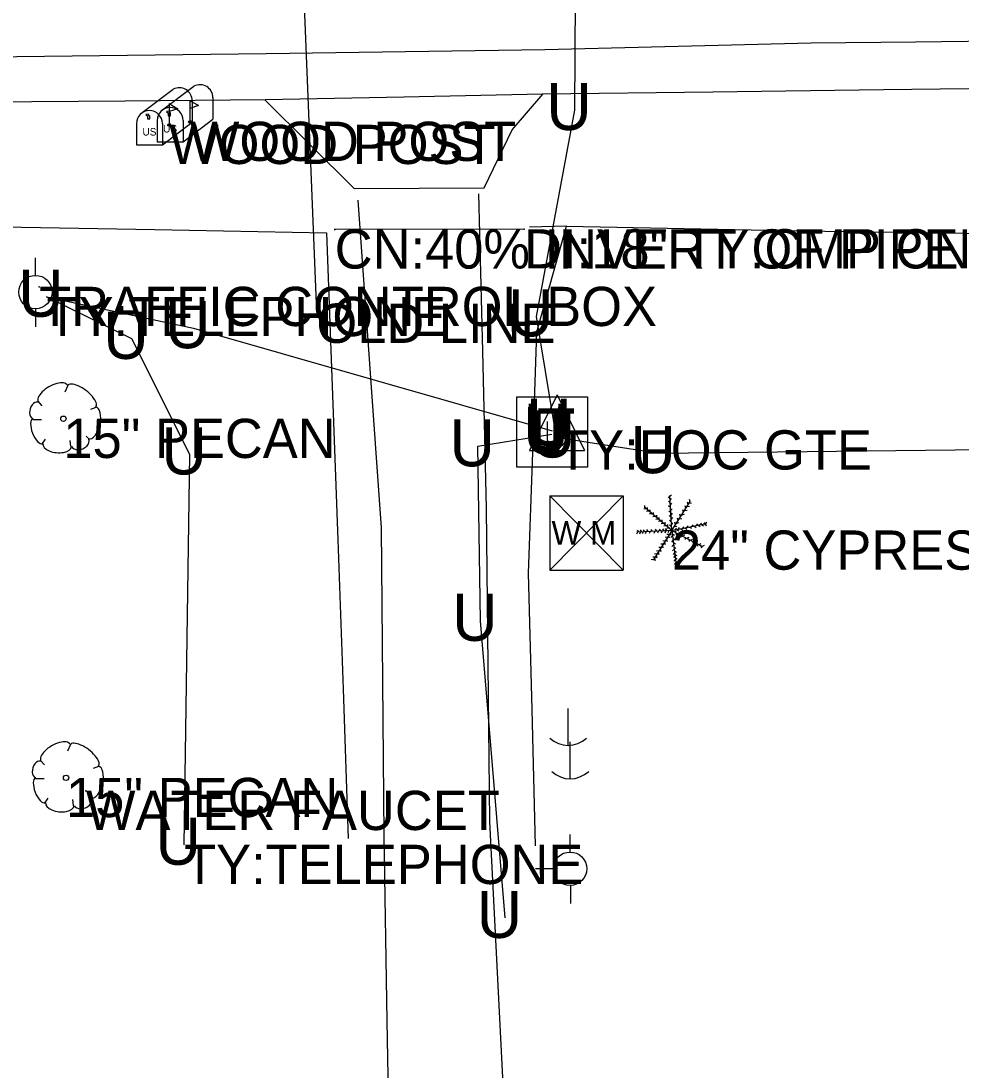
# Model space of a CAD drawing. Extents: x 1800653 to 1804042, y 522635 to 523313.
# Drawn here: x 1802896.5 to 1803016.3, y 522853.9 to 522987.6 of the extents above; entities that cross this region are included whole.
import ezdxf

# ---------------------------------------------------------------- set-up
doc = ezdxf.new("R2010")
doc.units = 0
for name, color, linetype in [('Default', 7, 'Continuous'), ('S_DITCHLINE', 7, 'Continuous'), ('S_DRG_PT_SYM', 7, 'Continuous'), ('S_EDGE_PAVEMENT', 7, 'Continuous'), ('S_GRAVEL_ROAD', 7, 'Continuous'), ('S_MAILBOX', 7, 'Continuous'), ('S_MAILBOX_ANNOT', 7, 'Continuous'), ('S_MSC_PT_SYM', 7, 'Continuous'), ('S_SANITARY_SEWER', 7, 'Continuous'), ('S_SANITARY_SEWER_ANNOT', 7, 'Continuous'), ('S_SHOULDER', 7, 'Continuous'), ('S_SIDE_DRAIN', 7, 'Continuous'), ('S_SIDE_DRAIN_ANNOT', 7, 'Continuous'), ('S_SURVEY_TEXT_ANNOT', 7, 'Continuous'), ('S_TELEPHONE_UTILITIES', 7, 'Continuous'), ('S_TREE', 7, 'Continuous'), ('S_TREE_ANNOT', 7, 'Continuous'), ('S_UNDERGROUND_CABLE', 7, 'Continuous'), ('S_UNDERGROUND_CABLE_ANNOT', 7, 'Continuous'), ('S_UTILITY_POLE', 7, 'Continuous'), ('S_UTILITY_POLE_ANNOT', 7, 'Continuous'), ('S_UTL_PT_SYM', 7, 'Continuous'), ('S_WATER_UTILITIES', 7, 'Continuous')]:
    doc.layers.add(name, color=color, linetype=linetype)

msp = doc.modelspace()

# ---------------------------------------------------------------- linework, layer by layer
at = {"layer": 'S_DITCHLINE'}
for points in [[(1802794.52, 522958.95), (1802809.08, 522959.6), (1802832.38, 522959.97), (1802855.67, 522960.34), (1802873.68, 522960.89), (1802891.69, 522961.44), (1802913.57, 522961.04), (1802935.44, 522960.63), (1802936.18, 522941.07), (1802936.91, 522921.5), (1802937.57, 522902.46), (1802938.23, 522883.42)], [(1802962.08, 522882.48), (1802961.64, 522899.88), (1802961.2, 522917.27), (1802961.74, 522932.63), (1802962.27, 522947.99), (1802966.05, 522961.46), (1802981.02, 522961.17), (1802996, 522960.89), (1803019.65, 522960.53), (1803023.7, 522960.83)], [(1802966.08, 522961.47), (1802961.32, 522961.36)]]:
    msp.add_lwpolyline(points, dxfattribs=at)
at = {"layer": 'S_DRG_PT_SYM'}
for points in [[(1802936.49, 522961.07), (1802936.49, 522961.12), (1802936.49, 522961.07), (1802936.44, 522961.07), (1802936.49, 522961.07), (1802936.49, 522961.02), (1802936.49, 522961.07), (1802936.54, 522961.07)], [(1802960.64, 522961.09), (1802960.64, 522961.14), (1802960.64, 522961.09), (1802960.59, 522961.09), (1802960.64, 522961.09), (1802960.64, 522961.04), (1802960.64, 522961.09), (1802960.69, 522961.09)]]:
    msp.add_lwpolyline(points, dxfattribs=at)
at = {"layer": 'S_EDGE_PAVEMENT'}
for points in [[(1802793.98, 522981.33), (1802808.56, 522981.56), (1802832.98, 522981.95), (1802857.39, 522982.34), (1802874.9, 522982.71), (1802892.4, 522983.08), (1802910.08, 522983.28), (1802927.76, 522983.47), (1802945.52, 522983.73), (1802963.29, 522983.99), (1802980.26, 522984.41), (1802997.22, 522984.84), (1803010.53, 522984.99), (1803023.83, 522985.13), (1803037.14, 522985.28), (1803050.45, 522985.42), (1803063.93, 522985.65), (1803077.42, 522985.88), (1803090.9, 522986.1), (1803104.39, 522986.33), (1803117.62, 522986.56), (1803130.85, 522986.79), (1803144.08, 522987.01)], [(1802927.57, 522977.59), (1802938.97, 522966.27), (1802955.56, 522966.37), (1802959.12, 522973.75), (1802963.01, 522978.32)]]:
    msp.add_lwpolyline(points, dxfattribs=at)
at = {"layer": 'S_GRAVEL_ROAD'}
for points in [[(1802939.44, 522964.79), (1802940.92, 522943.92), (1802942.41, 522923.04), (1802942.58, 522903.43), (1802942.74, 522883.82), (1802943.15, 522860.2), (1802943.56, 522836.59), (1802944.03, 522816.43), (1802944.5, 522796.27), (1802944.97, 522776.11), (1802945.44, 522755.95), (1802945.78, 522741.87), (1802946.11, 522727.8), (1802946.44, 522713.72), (1802946.77, 522699.64)], [(1802954.81, 522965.58), (1802955.31, 522945.54), (1802955.81, 522925.5), (1802956.03, 522905.55), (1802956.24, 522885.61), (1802957.46, 522861.32), (1802958.68, 522837.04), (1802958.8, 522823.18), (1802958.92, 522809.31), (1802959.04, 522795.45), (1802959.17, 522781.58), (1802958.84, 522768.07), (1802958.52, 522754.56), (1802958.93, 522740.82), (1802959.34, 522727.07), (1802959.75, 522713.32), (1802960.16, 522699.58)]]:
    msp.add_lwpolyline(points, dxfattribs=at)
at = {"layer": 'S_MAILBOX'}
for p, q in [((1802914.41, 522976.21), (1802918.55, 522979.32)), ((1802911.78, 522975.83), (1802915.91, 522978.94)), ((1802915.39, 522977.12), (1802915.39, 522974.4)), ((1802918.03, 522977.5), (1802918.03, 522974.79)), ((1802918.34, 522977.46), (1802918.34, 522974.75)), ((1802920.98, 522977.85), (1802920.98, 522975.13)), ((1802911.22, 522974.55), (1802911.22, 522971.84)), ((1802913.86, 522974.94), (1802913.86, 522972.22)), ((1802914.55, 522971.84), (1802918.34, 522974.75)), ((1802914.55, 522974.55), (1802914.55, 522971.84)), ((1802917.18, 522972.22), (1802920.98, 522975.13)), ((1802917.18, 522974.94), (1802917.18, 522972.22)), ((1802911.22, 522971.84), (1802914.55, 522971.84)), ((1802913.86, 522972.22), (1802917.18, 522972.22))]:
    msp.add_line(p, q, dxfattribs=at)
for points in [[(1802915.39, 522977.12), (1802916.5, 522976.45), (1802915.39, 522976.11)], [(1802918.03, 522977.5), (1802919.14, 522976.84), (1802918.03, 522976.49)], [(1802912.41, 522975.67), (1802912.63, 522975.53), (1802912.63, 522975.14), (1802912.93, 522975.14), (1802912.93, 522975.5), (1802912.74, 522975.75), (1802912.41, 522975.7)], [(1802915.04, 522976.05), (1802915.27, 522975.92), (1802915.27, 522975.53), (1802915.57, 522975.53), (1802915.57, 522975.89), (1802915.38, 522976.14), (1802915.04, 522976.08)]]:
    msp.add_lwpolyline(points, dxfattribs=at)
for centre, end in [((1802919.32, 522977.85), 117.5718), ((1802916.68, 522977.46), 117.5718), ((1802915.52, 522974.94), 180), ((1802912.88, 522974.55), 180)]:
    msp.add_arc(centre, 1.66, 0, end, dxfattribs=at)
for centre in [(1802915.39, 522974.4), (1802918.03, 522974.79)]:
    msp.add_ellipse(centre, major_axis=(0.145, 0.132), ratio=0.564646, dxfattribs=at)
at = {"layer": 'S_MSC_PT_SYM'}
for points in [[(1802898.82, 522953.75), (1802898.82, 522953.8), (1802898.82, 522953.75), (1802898.77, 522953.75), (1802898.82, 522953.75), (1802898.82, 522953.7), (1802898.82, 522953.75), (1802898.87, 522953.75)], [(1802904.79, 522889.51), (1802904.79, 522889.56), (1802904.79, 522889.51), (1802904.74, 522889.51), (1802904.79, 522889.51), (1802904.79, 522889.46), (1802904.79, 522889.51), (1802904.84, 522889.51)]]:
    msp.add_lwpolyline(points, dxfattribs=at)
at = {"layer": 'S_SANITARY_SEWER'}
msp.add_line((1802934.16, 522951.6), (1802931.11, 523028.65), dxfattribs=at)
at = {"layer": 'S_SHOULDER'}
msp.add_lwpolyline([(1802793.86, 522975.94), (1802808.36, 522976.14), (1802832.74, 522976.63), (1802857.12, 522977.13), (1802874.52, 522977.23), (1802891.91, 522977.33), (1802909.78, 522977.47), (1802927.64, 522977.61), (1802945.31, 522977.97), (1802962.99, 522978.33), (1802984.7, 522978.6), (1803006.42, 522978.88), (1803028.14, 522979.15), (1803049.85, 522979.42), (1803063.55, 522979.76), (1803077.25, 522980.09), (1803090.95, 522980.43), (1803104.65, 522980.76), (1803117.85, 522980.81), (1803131.05, 522980.86), (1803144.24, 522980.9)], dxfattribs=at)
at = {"layer": 'S_SIDE_DRAIN'}
msp.add_line((1802960.64, 522961.09), (1802936.49, 522961.07), dxfattribs=at)
at = {"layer": 'S_TELEPHONE_UTILITIES'}
msp.add_lwpolyline([(1802959.72, 522930.74), (1802959.72, 522939.74), (1802968.72, 522939.74), (1802968.72, 522930.74)], close=True, dxfattribs=at)
at = {"layer": 'S_TREE'}
for p, q in [((1802902.47, 522941.17), (1802902.08, 522940.32)), ((1802898.67, 522939.16), (1802899.18, 522938.58)), ((1802906.04, 522938.38), (1802905.38, 522938.11)), ((1802898.01, 522936.83), (1802899.14, 522936.83)), ((1802899.18, 522933.65), (1802899.64, 522934.35)), ((1802902.86, 522933.38), (1802902.78, 522934.16)), ((1802905.26, 522934.27), (1802904.8, 522934.7)), ((1802979.47, 522922.69), (1802979.2, 522927.13)), ((1802979.21, 522927.02), (1802979.4, 522927.25)), ((1802976.04, 522925.57), (1802976.04, 522925.87)), ((1802979.21, 522926.77), (1802978.99, 522926.97)), ((1802979.25, 522926.21), (1802979.02, 522926.41)), ((1802979.28, 522925.63), (1802979.05, 522925.83)), ((1802979.24, 522926.54), (1802979.43, 522926.77)), ((1802979.27, 522925.94), (1802979.46, 522926.17)), ((1802979.47, 522922.69), (1802981.81, 522926.37)), ((1802981.24, 522925.55), (1802981.15, 522925.83)), ((1802981.43, 522925.74), (1802981.73, 522925.78)), ((1802981.54, 522926), (1802981.45, 522926.29)), ((1802981.68, 522926.16), (1802981.97, 522926.2)), ((1802981.79, 522926.34), (1802981.7, 522926.63)), ((1802976.19, 522925.43), (1802975.89, 522925.39)), ((1802979.47, 522922.69), (1802976.01, 522925.6)), ((1802976.53, 522925.15), (1802976.23, 522925.13)), ((1802976.36, 522925.32), (1802976.36, 522925.62)), ((1802976.9, 522924.83), (1802976.6, 522924.81)), ((1802976.71, 522925.03), (1802976.71, 522925.33)), ((1802977.35, 522924.46), (1802977.05, 522924.43)), ((1802977.13, 522924.67), (1802977.13, 522924.97)), ((1802977.54, 522924.34), (1802977.54, 522924.64)), ((1802979.3, 522924.97), (1802979.08, 522925.17)), ((1802979.34, 522924.38), (1802979.12, 522924.58)), ((1802979.31, 522925.23), (1802979.5, 522925.46)), ((1802979.38, 522924.66), (1802979.56, 522924.9)), ((1802980.57, 522924.46), (1802980.48, 522924.75)), ((1802980.79, 522924.7), (1802981.08, 522924.75)), ((1802980.95, 522925.03), (1802980.86, 522925.32)), ((1802981.11, 522925.24), (1802981.41, 522925.29)), ((1802977.71, 522924.13), (1802977.42, 522924.1)), ((1802978.05, 522923.86), (1802977.75, 522923.84)), ((1802977.86, 522924.06), (1802977.86, 522924.36)), ((1802978.39, 522923.57), (1802978.09, 522923.54)), ((1802978.23, 522923.75), (1802978.23, 522924.05)), ((1802978.76, 522923.27), (1802978.46, 522923.25)), ((1802978.6, 522923.45), (1802978.6, 522923.75)), ((1802978.95, 522923.14), (1802978.95, 522923.44)), ((1802979.38, 522923.81), (1802979.15, 522924.01)), ((1802979.39, 522923.19), (1802979.17, 522923.39)), ((1802979.39, 522924.09), (1802979.58, 522924.33)), ((1802979.41, 522923.42), (1802979.6, 522923.66)), ((1802979.47, 522922.69), (1802983.89, 522923.56)), ((1802979.82, 522923.18), (1802980.11, 522923.22)), ((1802979.91, 522923.44), (1802979.83, 522923.73)), ((1802980.1, 522923.64), (1802980.4, 522923.69)), ((1802980.28, 522923.97), (1802980.19, 522924.26)), ((1802980.44, 522924.19), (1802980.73, 522924.23)), ((1802980.78, 522922.94), (1802980.98, 522923.16)), ((1802981.34, 522923.07), (1802981.54, 522923.29)), ((1802981.73, 522923.13), (1802981.98, 522922.97)), ((1802981.98, 522923.21), (1802982.18, 522923.43)), ((1802982.31, 522923.23), (1802982.56, 522923.07)), ((1802982.57, 522923.3), (1802982.77, 522923.52)), ((1802982.82, 522923.35), (1802983.07, 522923.19)), ((1802983.05, 522923.4), (1802983.25, 522923.62)), ((1802983.24, 522923.44), (1802983.5, 522923.28)), ((1802983.5, 522923.49), (1802983.7, 522923.71)), ((1802983.65, 522923.5), (1802983.9, 522923.34)), ((1802983.72, 522923.54), (1802983.93, 522923.76)), ((1802975.1, 522922.48), (1802974.97, 522922.21)), ((1802979.47, 522922.69), (1802975.02, 522922.48)), ((1802975.25, 522922.5), (1802975.08, 522922.75)), ((1802975.45, 522922.5), (1802975.32, 522922.23)), ((1802975.64, 522922.53), (1802975.47, 522922.77)), ((1802975.79, 522922.52), (1802975.66, 522922.25)), ((1802976.04, 522922.53), (1802975.87, 522922.77)), ((1802976.21, 522922.54), (1802976.08, 522922.27)), ((1802976.44, 522922.55), (1802976.27, 522922.8)), ((1802976.72, 522922.56), (1802976.59, 522922.29)), ((1802977.01, 522922.57), (1802976.84, 522922.81)), ((1802979.47, 522922.69), (1802977.09, 522918.92)), ((1802977.28, 522922.59), (1802977.15, 522922.32)), ((1802977.56, 522922.6), (1802977.39, 522922.85)), ((1802977.77, 522922.61), (1802977.63, 522922.34)), ((1802978.04, 522922.62), (1802977.87, 522922.87)), ((1802978.24, 522922.63), (1802978.1, 522922.36)), ((1802978.48, 522922.66), (1802978.31, 522922.9)), ((1802978.7, 522922.64), (1802978.56, 522922.37)), ((1802978.9, 522921.83), (1802978.6, 522921.79)), ((1802978.81, 522922.69), (1802978.64, 522922.94)), ((1802979.12, 522922.97), (1802978.82, 522922.95)), ((1802979.14, 522922.19), (1802978.84, 522922.16)), ((1802979.08, 522922.65), (1802978.95, 522922.38)), ((1802979.05, 522922.03), (1802979.13, 522921.74)), ((1802979.26, 522922.37), (1802979.34, 522922.08)), ((1802979.53, 522922.01), (1802979.34, 522921.79)), ((1802979.47, 522922.69), (1802983.39, 522920.64)), ((1802979.47, 522922.69), (1802980, 522918.32)), ((1802979.55, 522922.26), (1802979.8, 522922.11)), ((1802979.8, 522922.51), (1802980.06, 522922.65)), ((1802979.85, 522922.77), (1802980.05, 522923)), ((1802979.98, 522922.41), (1802980.05, 522922.12)), ((1802980.09, 522922.81), (1802980.34, 522922.65)), ((1802980.25, 522922.83), (1802980.45, 522923.05)), ((1802980.28, 522922.28), (1802980.54, 522922.42)), ((1802980.56, 522922.11), (1802980.63, 522921.82)), ((1802980.61, 522922.88), (1802980.86, 522922.72)), ((1802980.83, 522921.98), (1802981.1, 522922.12)), ((1802981.1, 522921.83), (1802981.17, 522921.54)), ((1802981.12, 522923), (1802981.37, 522922.84)), ((1802981.39, 522921.7), (1802981.65, 522921.84)), ((1802978.11, 522920.54), (1802977.81, 522920.51)), ((1802978.37, 522920.96), (1802978.07, 522920.93)), ((1802978.26, 522920.75), (1802978.33, 522920.46)), ((1802978.62, 522921.38), (1802978.33, 522921.35)), ((1802978.51, 522921.18), (1802978.59, 522920.89)), ((1802978.77, 522921.59), (1802978.85, 522921.3)), ((1802979.6, 522921.43), (1802979.4, 522921.21)), ((1802979.68, 522920.87), (1802979.48, 522920.64)), ((1802979.59, 522921.71), (1802979.84, 522921.55)), ((1802979.67, 522921.14), (1802979.93, 522920.99)), ((1802979.73, 522920.59), (1802979.99, 522920.44)), ((1802981.62, 522921.56), (1802981.69, 522921.27)), ((1802981.87, 522921.44), (1802982.13, 522921.58)), ((1802982.15, 522921.26), (1802982.22, 522920.97)), ((1802982.41, 522921.17), (1802982.67, 522921.31)), ((1802982.67, 522921.01), (1802982.74, 522920.71)), ((1802982.95, 522920.89), (1802983.22, 522921.03)), ((1802983.16, 522920.75), (1802983.23, 522920.46)), ((1802983.35, 522920.68), (1802983.61, 522920.82)), ((1802977.32, 522919.3), (1802977.02, 522919.27)), ((1802977.24, 522919.16), (1802977.32, 522918.87)), ((1802977.57, 522919.72), (1802977.27, 522919.68)), ((1802977.47, 522919.51), (1802977.55, 522919.22)), ((1802977.81, 522920.09), (1802977.51, 522920.06)), ((1802977.73, 522919.91), (1802977.8, 522919.62)), ((1802977.97, 522920.29), (1802978.05, 522920)), ((1802979.75, 522920.3), (1802979.55, 522920.08)), ((1802979.82, 522919.85), (1802979.62, 522919.62)), ((1802979.85, 522919.47), (1802979.66, 522919.24)), ((1802979.81, 522920.08), (1802980.06, 522919.93)), ((1802979.84, 522919.65), (1802980.09, 522919.5)), ((1802979.88, 522919.24), (1802980.14, 522919.09)), ((1802977.12, 522919), (1802976.82, 522918.97)), ((1802979.91, 522919.02), (1802979.72, 522918.79)), ((1802979.96, 522918.6), (1802979.76, 522918.37)), ((1802979.95, 522918.78), (1802980.2, 522918.62)), ((1802979.99, 522918.44), (1802980.24, 522918.28)), ((1802902.81, 522895.4), (1802902.42, 522894.55)), ((1802899.01, 522893.39), (1802899.52, 522892.81)), ((1802906.38, 522892.61), (1802905.72, 522892.34)), ((1802898.35, 522891.06), (1802899.48, 522891.06)), ((1802899.52, 522887.88), (1802899.98, 522888.58)), ((1802903.2, 522887.61), (1802903.12, 522888.39)), ((1802905.6, 522888.5), (1802905.14, 522888.93))]:
    msp.add_line(p, q, dxfattribs=at)
for centre in [(1802901.91, 522936.93), (1802902.25, 522891.16)]:
    msp.add_circle(centre, 0.341, dxfattribs=at)
for centre, major_axis, ratio, start_param, end_param in [((1802900.58, 522940.13), (1.86, 1.08), 0.471018, 0, 3.141593), ((1802904.23, 522939.8), (-1.81, 1.36), 0.405113, 3.141593, 6.283186), ((1802898.34, 522938.01), (0.31, 1.03), 0.646762, 0, 3.141593), ((1802905.59, 522936.4), (0.46, 2.04), 0.482994, 3.141593, 6.283185), ((1802898.65, 522935.36), (-0.61, 1.6), 0.420543, 6.283185, 9.424777), ((1802901.11, 522933.58), (-1.83, 0.19), 0.529943, 0, 3.141593), ((1802904.06, 522933.88), (1.09, 0.46), 0.711534, 3.141592, 6.283185), ((1802900.92, 522894.36), (1.86, 1.08), 0.471018, 0, 3.141593), ((1802904.57, 522894.03), (-1.81, 1.36), 0.405113, 3.141593, 6.283186), ((1802898.68, 522892.24), (0.31, 1.03), 0.646762, 0, 3.141593), ((1802905.93, 522890.63), (0.46, 2.04), 0.482994, 3.141593, 6.283185), ((1802898.99, 522889.59), (-0.61, 1.6), 0.420543, 6.283185, 9.424777), ((1802904.4, 522888.11), (1.09, 0.46), 0.711534, 3.141592, 6.283185), ((1802901.45, 522887.81), (-1.83, 0.19), 0.529943, 0, 3.141593)]:
    msp.add_ellipse(centre, major_axis=major_axis, ratio=ratio, start_param=start_param, end_param=end_param, dxfattribs=at)
at = {"layer": 'S_UNDERGROUND_CABLE'}
for p, q in [((1802967.09, 522976.27), (1802967.36, 523010.8)), ((1802962.2, 522949.97), (1802967.09, 522976.27)), ((1802910.63, 522947.1), (1802899.78, 522952.47)), ((1802899.78, 522952.47), (1802918.5, 522948.47)), ((1802964.52, 522936.04), (1802962.2, 522949.97)), ((1802918.5, 522948.47), (1802964.21, 522935.39)), ((1802918.03, 522932.38), (1802910.63, 522947.1)), ((1802964.84, 522939.99), (1802961.31, 522932.9)), ((1802964.84, 522939.99), (1802968.32, 522932.9)), ((1802963.63, 522934.14), (1802963.63, 522936.58)), ((1802966, 522936.58), (1802966, 522934.14)), ((1802954.75, 522933.42), (1802964.16, 522934.98)), ((1802964.25, 522933.48), (1802963.63, 522934.14)), ((1802964.99, 522934.53), (1802977.79, 522932.53)), ((1802966, 522934.14), (1802965.46, 522933.48)), ((1802955.09, 522911.17), (1802954.75, 522933.42)), ((1802961.31, 522932.9), (1802968.32, 522932.9)), ((1802965.46, 522933.48), (1802964.25, 522933.48)), ((1802977.79, 522932.53), (1803040.79, 522933.26)), ((1802917.29, 522882.63), (1802918.03, 522932.38)), ((1802958.22, 522873.31), (1802955.09, 522911.17))]:
    msp.add_line(p, q, dxfattribs=at)
at = {"layer": 'S_UTILITY_POLE'}
for p, q in [((1802898.34, 522955.2), (1802898.34, 522957.44)), ((1802898.42, 522948.65), (1802898.42, 522950.97)), ((1802966.19, 522900), (1802966.19, 522895.27)), ((1802966.45, 522895.75), (1802966.45, 522891.02)), ((1802966.49, 522881.69), (1802966.49, 522883.93)), ((1802964.4, 522879.56), (1802962.07, 522879.56)), ((1802966.57, 522875.14), (1802966.57, 522877.46))]:
    msp.add_line(p, q, dxfattribs=at)
for centre in [(1802898.35, 522953.08), (1802966.49, 522879.58)]:
    msp.add_circle(centre, 2.13, dxfattribs=at)
for centre in [(1802966.25, 522898.7), (1802966.51, 522894.45)]:
    msp.add_arc(centre, 3.41, 226.3972, 313.6028, dxfattribs=at)
at = {"layer": 'S_UTL_PT_SYM'}
msp.add_lwpolyline([(1802934.16, 522951.6), (1802934.16, 522951.65), (1802934.16, 522951.6), (1802934.11, 522951.6), (1802934.16, 522951.6), (1802934.16, 522951.55), (1802934.16, 522951.6), (1802934.21, 522951.6)], dxfattribs=at)
at = {"layer": 'S_WATER_UTILITIES'}
for p, q in [((1802963.92, 522927.12), (1802973.26, 522927.12)), ((1802963.92, 522927.12), (1802963.92, 522917.63)), ((1802963.92, 522927.12), (1802973.26, 522917.63)), ((1802973.26, 522927.12), (1802963.92, 522917.63)), ((1802973.26, 522927.12), (1802973.26, 522917.63)), ((1802963.92, 522917.63), (1802973.26, 522917.63))]:
    msp.add_line(p, q, dxfattribs=at)

# ---------------------------------------------------------------- texts
at = {"layer": 'Default'}
for p in [(1802963.46, 522973.73), (1802896.15, 522949.93), (1802896.15, 522949.93), (1802958.58, 522947.42), (1802914.87, 522945.92), (1802907, 522944.56), (1802960.89, 522933.5), (1802960.53, 522932.43), (1802960.58, 522932.85), (1802961.36, 522931.99), (1802951.12, 522930.87), (1802914.4, 522929.83), (1802974.17, 522929.99), (1802951.46, 522908.62), (1802913.66, 522880.08), (1802954.59, 522870.76)]:
    msp.add_text('U', height=6, dxfattribs=at).set_placement(p)
at = {"layer": 'S_MAILBOX'}
for p in [(1802911.99, 522973.03), (1802914.62, 522973.42)]:
    msp.add_text('US', height=0.96, dxfattribs=at).set_placement(p)
at = {"layer": 'S_MAILBOX_ANNOT'}
for p in [(1802915.39, 522969.4), (1802918.03, 522969.79)]:
    msp.add_text('WOOD POST', height=5, dxfattribs=at).set_placement(p)
at = {"layer": 'S_SANITARY_SEWER_ANNOT'}
msp.add_text('OLD LINE', height=5, dxfattribs=at).set_placement((1802934.16, 522946.6))
at = {"layer": 'S_SIDE_DRAIN_ANNOT'}
for s, p in [('CN:40% INVERT OF PIPE', (1802936.49, 522956.07)), ('DI:18" TY:CMP CN:75% LN:24\' INV', (1802960.64, 522956.09))]:
    msp.add_text(s, height=5, dxfattribs=at).set_placement(p)
at = {"layer": 'S_SURVEY_TEXT_ANNOT'}
for s, p in [('TRAFFIC CONTROL BOX', (1802898.82, 522948.75)), ('WATER FAUCET', (1802904.79, 522884.51))]:
    msp.add_text(s, height=5, dxfattribs=at).set_placement(p)
at = {"layer": 'S_TELEPHONE_UTILITIES'}
msp.add_text('T', height=6, dxfattribs=at).set_placement((1802962.28, 522932.24))
at = {"layer": 'S_TREE_ANNOT'}
for s, p in [('15" PECAN', (1802901.91, 522931.93)), ('24" CYPRESS', (1802979.47, 522917.69)), ('15" PECAN', (1802902.25, 522886.16))]:
    msp.add_text(s, height=5, dxfattribs=at).set_placement(p)
at = {"layer": 'S_UNDERGROUND_CABLE_ANNOT'}
for p in [(1802899.78, 522947.47), (1802917.29, 522877.63)]:
    msp.add_text('TY:TELEPHONE', height=5, dxfattribs=at).set_placement(p)
at = {"layer": 'S_UTILITY_POLE_ANNOT'}
msp.add_text('TY:FOC GTE', height=5, dxfattribs=at).set_placement((1802964.84, 522930.46))
at = {"layer": 'S_WATER_UTILITIES'}
msp.add_text('W M', height=3, dxfattribs=at).set_placement((1802964.13, 522920.89))

doc.saveas('drawing.dxf')
